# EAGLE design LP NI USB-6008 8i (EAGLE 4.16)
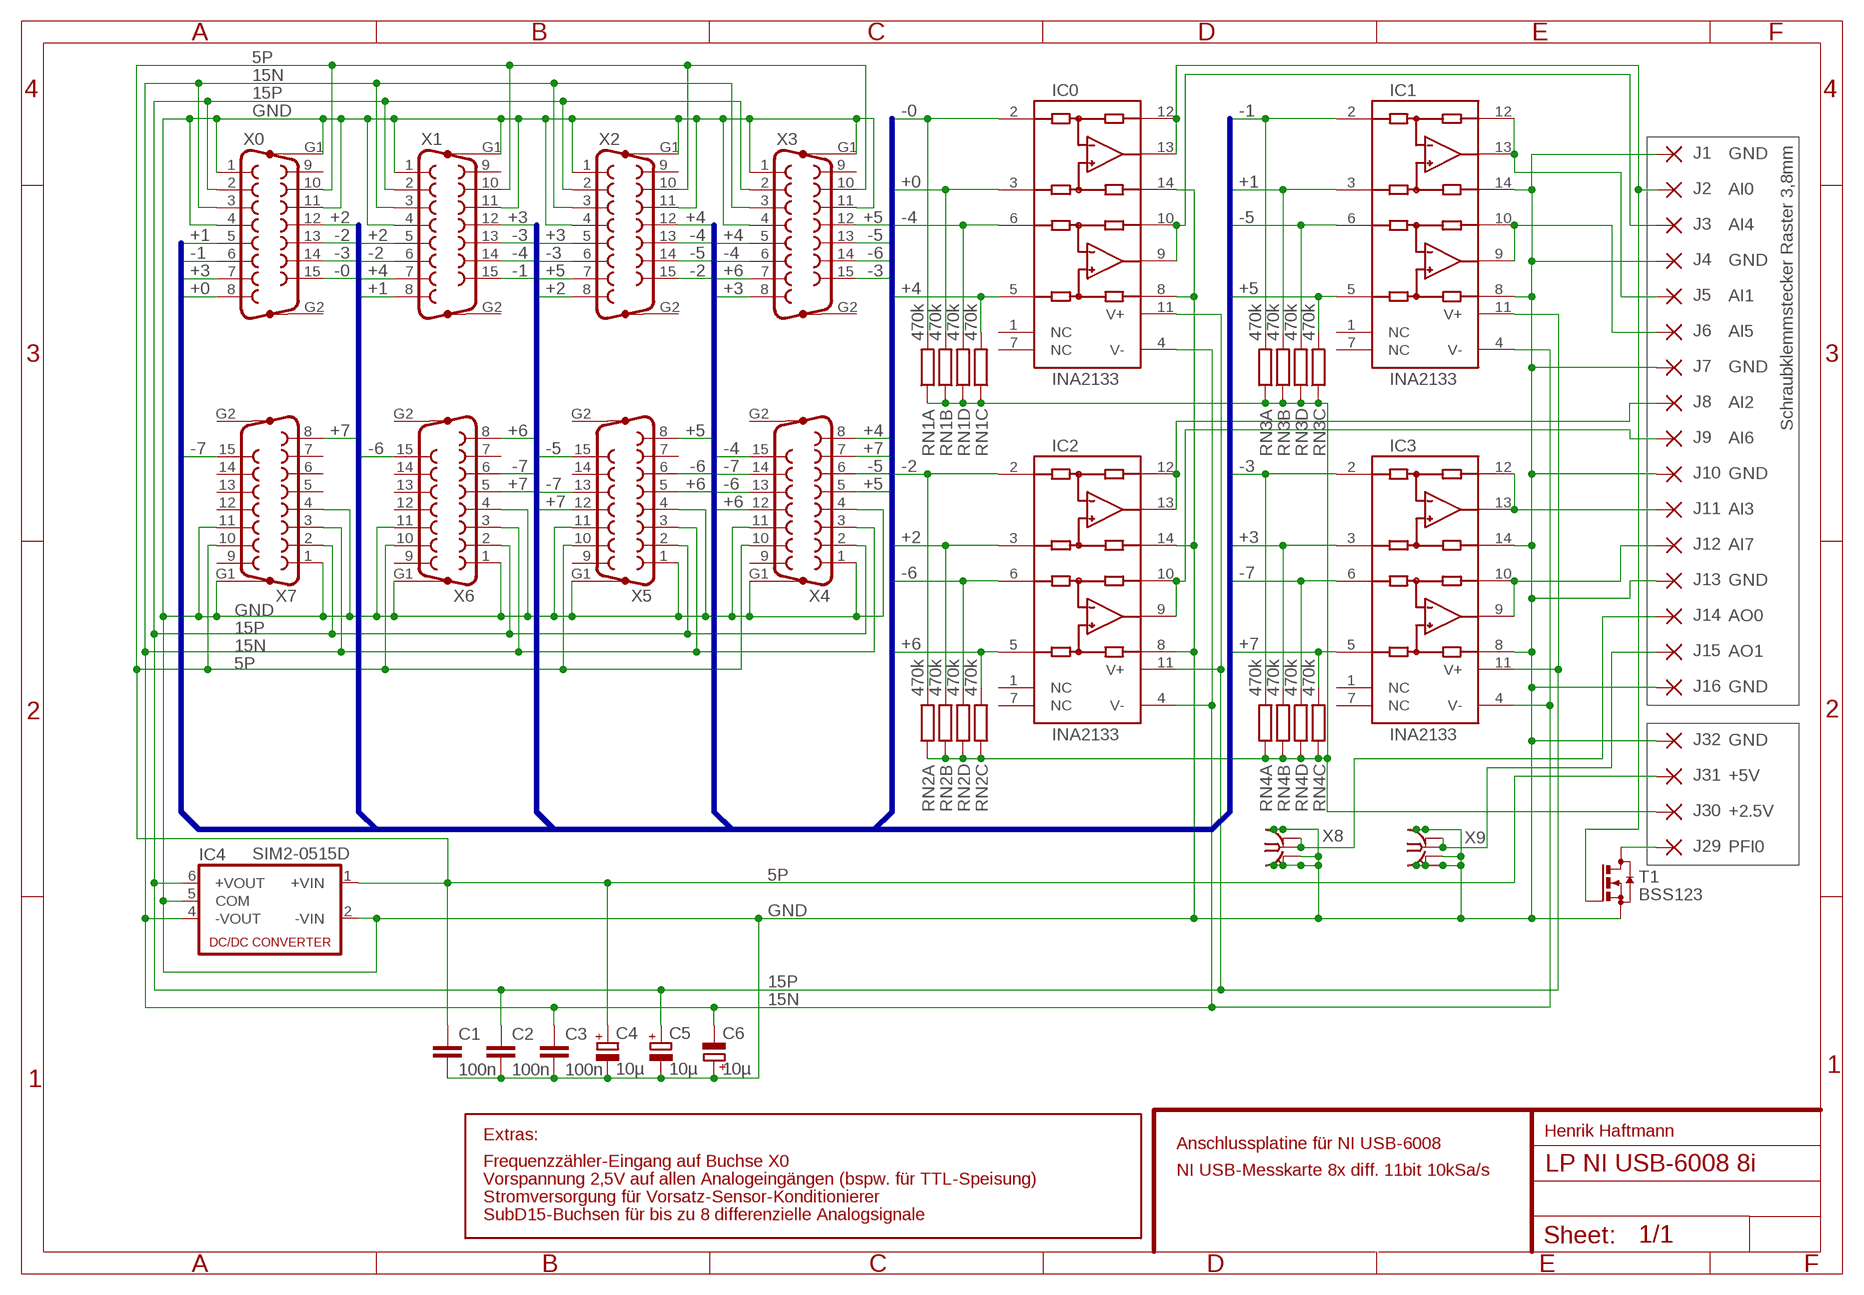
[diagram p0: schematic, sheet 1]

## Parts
C1  100n  C-EUC0603K  [C0603K]
C2  100n  C-EUC0603K  [C0603K]
C3  100n  C-EUC0603K  [C0603K]
C4  10µ  CPOL-EUE2.5-6  [E2,5-6]
C5  10µ  CPOL-EUE2.5-6  [E2,5-6]
C6  10µ  CPOL-EUE2.5-6  [E2,5-6]
IC0  INA2133  INA2134U  [SO14]
IC1  INA2133  INA2134U  [SO14]
IC2  INA2133  INA2134U  [SO14]
IC3  INA2133  INA2134U  [SO14]
IC4  SIM2-0515D  NMA  [NMA]
J1  GND  WIREPAD2,54/1,0  [2,54/1,0]
J2  AI0  WIREPAD2,54/1,0  [2,54/1,0]
J3  AI4  WIREPAD2,54/1,0  [2,54/1,0]
J4  GND  WIREPAD2,54/1,0  [2,54/1,0]
J5  AI1  WIREPAD2,54/1,0  [2,54/1,0]
J6  AI5  WIREPAD2,54/1,0  [2,54/1,0]
J7  GND  WIREPAD2,54/1,0  [2,54/1,0]
J8  AI2  WIREPAD2,54/1,0  [2,54/1,0]
J9  AI6  WIREPAD2,54/1,0  [2,54/1,0]
J10  GND  WIREPAD2,54/1,0  [2,54/1,0]
J11  AI3  WIREPAD2,54/1,0  [2,54/1,0]
J12  AI7  WIREPAD2,54/1,0  [2,54/1,0]
J13  GND  WIREPAD2,54/1,0  [2,54/1,0]
J14  AO0  WIREPAD2,54/1,0  [2,54/1,0]
J15  AO1  WIREPAD2,54/1,0  [2,54/1,0]
J16  GND  WIREPAD2,54/1,0  [2,54/1,0]
J29  PFI0  WIREPAD2,54/1,0  [2,54/1,0]
J30  +2.5V  WIREPAD2,54/1,0  [2,54/1,0]
J31  +5V  WIREPAD2,54/1,0  [2,54/1,0]
J32  GND  WIREPAD2,54/1,0  [2,54/1,0]
RN1  470k  RN-4P1206  [R-4P]
RN2  470k  RN-4P1206  [R-4P]
RN3  470k  RN-4P1206  [R-4P]
RN4  470k  RN-4P1206  [R-4P]
T1  BSS123  [SOT23]
X0  F15VP  [F15VP]
X1  F15VP  [F15VP]
X2  F15VP  [F15VP]
X3  F15VP  [F15VP]
X4  F15VP  [F15VP]
X5  F15VP  [F15VP]
X6  F15VP  [F15VP]
X7  F15VP  [F15VP]
X8  BU-BNC  [BU-BNC]
X9  BU-BNC  [BU-BNC]

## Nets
2P5: J30.1(P) RN1.1 RN1.2 RN1.3 RN1.4 RN2.1 RN2.2 RN2.3 RN2.4 RN3.1 RN3.2 RN3.3 RN3.4 RN4.1 RN4.2 RN4.3 RN4.4
5P: C1.1 C4.+ IC4.1(+VIN) J31.1(P) X0.10 X1.10 X2.10 X3.10 X4.10 X5.10 X6.10 X7.10
15N: C3.1 C6.- IC0.4(V-) IC1.4(V-) IC2.4(V-) IC3.4(V-) IC4.4(-VOUT) X0.3 X1.3 X2.3 X3.3 X4.3 X5.3 X6.3 X7.3
15P: C2.1 C5.+ IC0.11(V+) IC1.11(V+) IC2.11(V+) IC3.11(V+) IC4.6(+VOUT) X0.2 X1.2 X2.2 X3.2 X4.2 X5.2 X6.2 X7.2
+0: IC0.3(+INA) RN1.7 X0.8
+1: IC1.3(+INA) RN3.7 X0.5 X1.8
+2: IC2.3(+INA) RN2.7 X0.12 X1.5 X2.8
+3: IC3.3(+INA) RN4.7 X0.7 X1.12 X2.5 X3.8
+4: IC0.5(+INB) RN1.6 X1.7 X2.12 X3.5 X4.8
+5: IC1.5(+INB) RN3.6 X2.7 X3.12 X4.5 X5.8
+6: IC2.5(+INB) RN2.6 X3.7 X4.12 X5.5 X6.8
+7: IC3.5(+INB) RN4.6 X4.7 X5.12 X6.5 X7.8
-0: IC0.2(-INA) RN1.8 X0.15
-1: IC1.2(-INA) RN3.8 X0.6 X1.15
-2: IC2.2(-INA) RN2.8 X0.13 X1.6 X2.15
-3: IC3.2(-INA) RN4.8 X0.14 X1.13 X2.6 X3.15
-4: IC0.6(-INB) RN1.5 X1.14 X2.13 X3.6 X4.15
-5: IC1.6(-INB) RN3.5 X2.14 X3.13 X4.6 X5.15
-6: IC2.6(-INB) RN2.5 X3.14 X4.13 X5.6 X6.15
-7: IC3.6(-INB) RN4.5 X4.14 X5.13 X6.6 X7.15
AI0: IC0.12(SENSEA) IC0.13(OUTA) J2.1(P) T1.1(G)
AI1: IC1.12(SENSEA) IC1.13(OUTA) J5.1(P)
AI2: IC2.12(SENSEA) IC2.13(OUTA) J8.1(P)
AI3: IC3.12(SENSEA) IC3.13(OUTA) J11.1(P)
AI4: IC0.9(OUTB) IC0.10(SENSEB) J3.1(P)
AI5: IC1.9(OUTB) IC1.10(SENSEB) J6.1(P)
AI6: IC2.9(OUTB) IC2.10(SENSEB) J9.1(P)
AI7: IC3.9(OUTB) IC3.10(SENSEB) J12.1(P)
AO0: J14.1(P) X8.1 X8.1A
AO1: J15.1(P) X9.1 X9.1A
GND: C1.2 C2.2 C3.2 C4.- C5.- C6.+ IC0.8(REFB) IC0.14(REFA) IC1.8(REFB) IC1.14(REFA) IC2.8(REFB) IC2.14(REFA) IC3.8(REFB) IC3.14(REFA) IC4.2(-VIN) IC4.5(COM) J1.1(P) J4.1(P) J7.1(P) J10.1(P) J13.1(P) J16.1(P) J32.1(P) T1.2(S) X0.1 X0.4 X0.11 X0.G1 X1.1 X1.4 X1.11 X1.G1 X2.1 X2.4 X2.11 X2.G1 X3.1 X3.4 X3.11 X3.G1 X4.1 X4.4 X4.11 X4.G1 X5.1 X5.4 X5.11 X5.G1 X6.1 X6.4 X6.11 X6.G1 X7.1 X7.4 X7.11 X7.G1 X8.2 X8.2A X8.3 X8.3A X8.3B X8.4 X8.4A X8.4B X9.2 X9.2A X9.3 X9.3A X9.3B X9.4 X9.4A X9.4B
N$1: J29.1(P) T1.3(D)
Unconnected: IC0.1(NC) IC0.7(NC) IC1.1(NC) IC1.7(NC) IC2.1(NC) IC2.7(NC) IC3.1(NC) IC3.7(NC) X0.9 X0.G2 X1.9 X1.G2 X2.9 X2.G2 X3.9 X3.G2 X4.9 X4.G2 X5.7 X5.9 X5.14 X5.G2 X6.7 X6.9 X6.12 X6.13 X6.14 X6.G2 X7.5 X7.6 X7.7 X7.9 X7.12 X7.13 X7.14 X7.G2

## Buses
+[0..7],-[0..7]

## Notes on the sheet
- Schraubklemmstecker Raster 3,8mm
- Extras: | Henrik Haftmann
- Anschlussplatine für NI USB-6008
- Frequenzzähler-Eingang auf Buchse X0
- NI USB-Messkarte 8x diff. 11bit 10kSa/s
- Vorspannung 2,5V auf allen Analogeingängen (bspw. für TTL-Speisung)
- Stromversorgung für Vorsatz-Sensor-Konditionierer
- SubD15-Buchsen für bis zu 8 differenzielle Analogsignale

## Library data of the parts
C1-C3 = rcl:C-EU: CAPACITOR, European symbol
C4-C6 = rcl:CPOL-EU: POLARIZED CAPACITOR, European symbol
IC0 IC1-IC3 = burr-brown:INA2134: Audio Differential Line Receivers 0dB, G=1
IC4 = dc-dc-converter:NMA: DC-DC CONVERTER
J1-J16 J29-J32 = wirepad:WIREPAD: Wire PAD connect wire on PCB
RN1-RN4 = DiffV:RN-4P: Widerstandsnetzwerk 4 Parallel
T1 = transistor-small-signal:BSS123: N-CHANNEL MOS FET
X0 X1-X7 = con-subd:F15VP: SUB-D
X8 X9 = Trigger-EA:BU-BNC: BNC-Buchse von Schneider

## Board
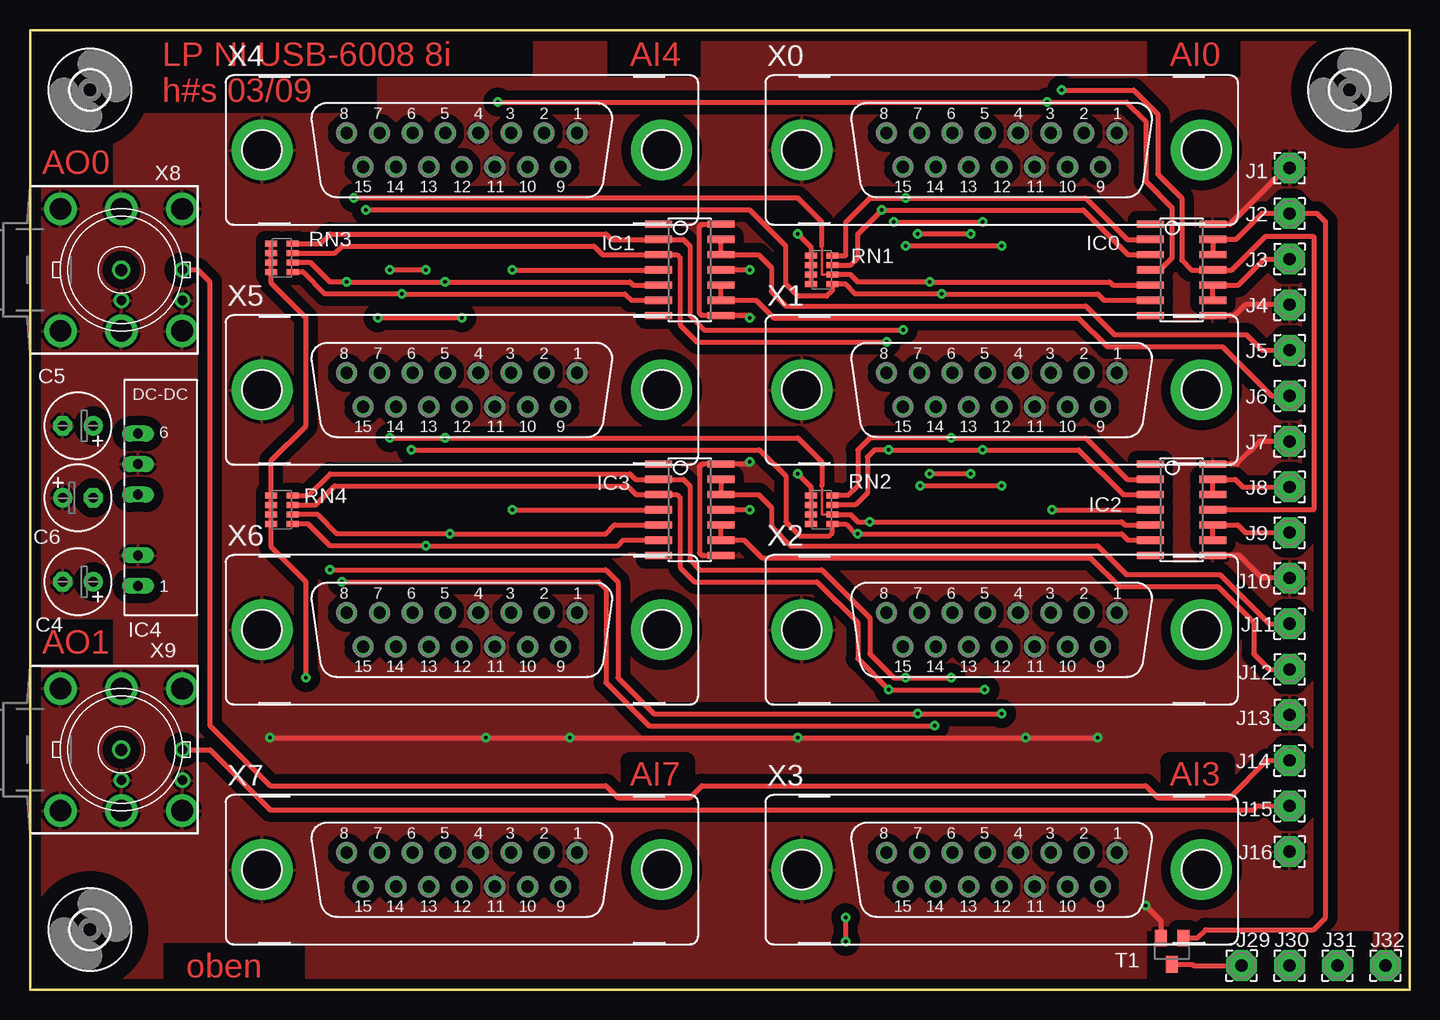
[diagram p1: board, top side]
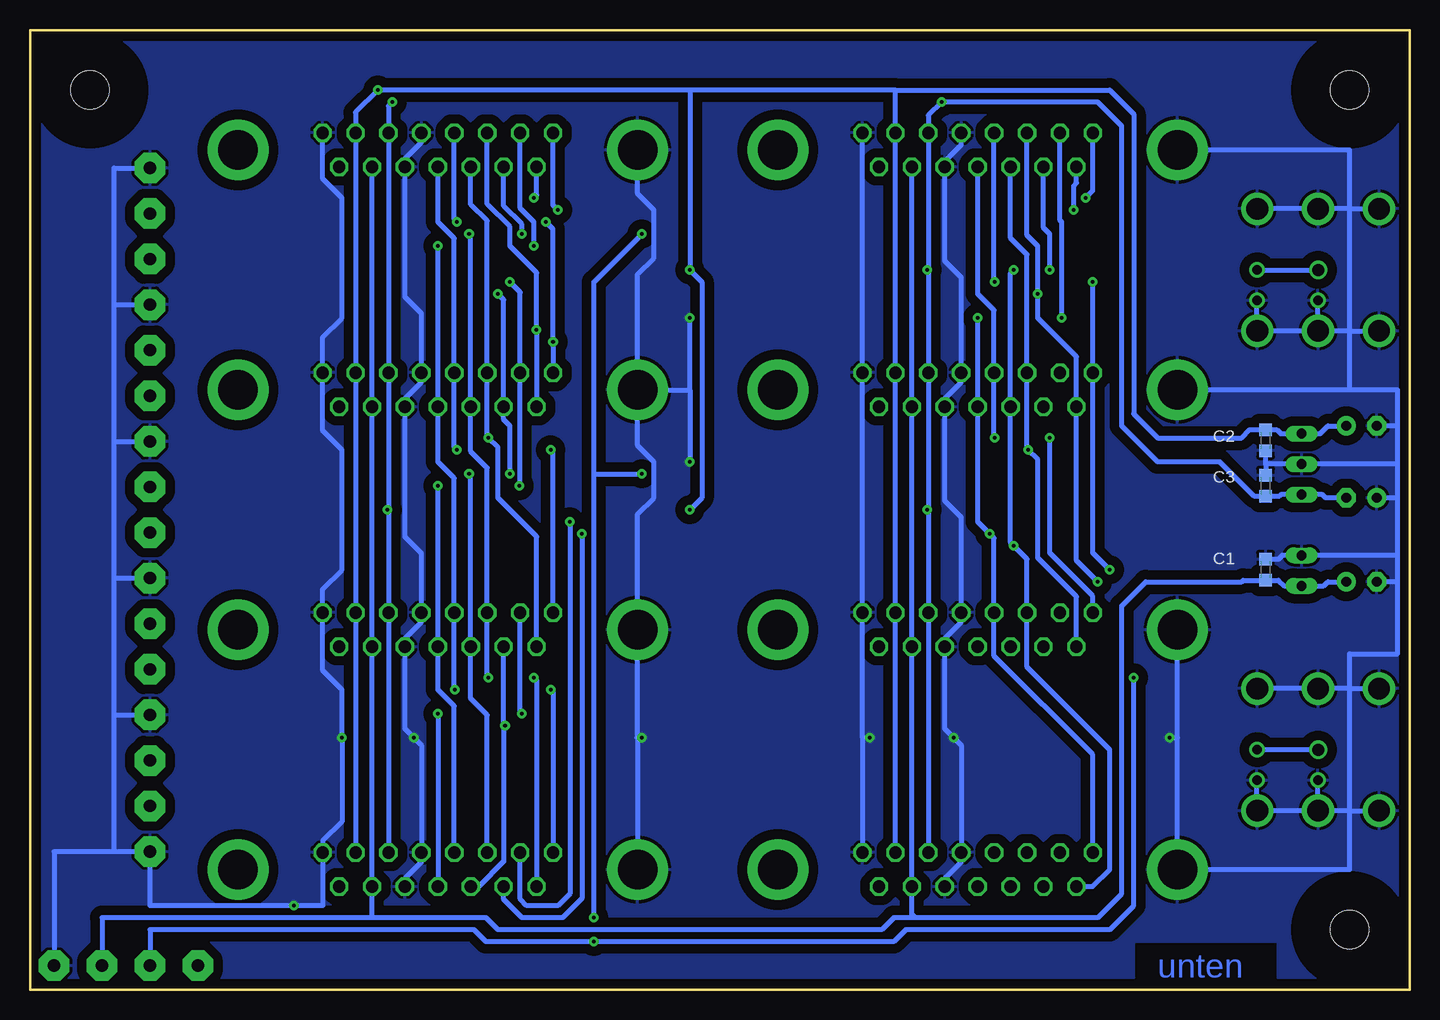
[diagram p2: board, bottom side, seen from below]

Size 115 x 80 mm. Coordinates in mm from the lower left corner, seen from the top.
Outline: 0,0 115,0 115,80 0,80 0,0
Copper layers (1*16): Top 0.035mm / dielectric 1.5mm / Bottom 0.035mm
Design rules "Felber": minimum track width 0.15mm, minimum drill 0.3mm, track to track 0.15mm, track to pad 0.15mm, pad to pad 0.15mm, via to via 0.15mm, smd to smd 0mil, copper to edge 0.3mm, drill to drill 0.3mm, minimum pad ring 10mil, minimum via ring 8mil, stop-mask expansion 4mil, vias tented up to drill 0mil, thermal gap 10mil

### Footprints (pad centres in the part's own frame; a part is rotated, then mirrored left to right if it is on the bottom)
C0603K = smd 1.05 x 1.08: 1 -0.875,0; 2 0.875,0
E2,5-6 = drill 0.813 pad 1.6 round: + -1.27,0 | drill 0.813 pad 1.6 octagon: - 1.27,0
SO14 = smd 0.61 x 2.21: 1 -3.81,-2.603; 2 -2.54,-2.603; 3 -1.27,-2.603; 4 0,-2.603; 5 1.27,-2.603; 6 2.54,-2.603; 7 3.81,-2.603; 8 3.81,2.603; 9 2.54,2.603; 10 1.27,2.603; 11 0,2.603; 12 -1.27,2.603; 13 -2.54,2.603; 14 -3.81,2.603
NMA = drill 0.813 long: 1 0,6.35; 2 0,3.81; 4 0,-1.27; 5 0,-3.81; 6 0,-6.35
2,54/1,0 = drill 1.016 pad 2.54 octagon: 1 0,0
R-4P = smd 0.5 x 1: 1 -1.2,-0.88; 2 -0.4,-0.88; 3 0.4,-0.88; 4 1.2,-0.88; 5 1.2,0.88; 6 0.4,0.88; 7 -0.4,0.88; 8 -1.2,0.88
SOT23 = smd 1 x 1.4: 1 -0.95,-1.1; 2 0.95,-1.1; 3 0,1.1
3,2 = hole 3.2: 0,0
F15VP = drill 1.016 octagon: 1 9.601,1.422; 2 6.858,1.422; 3 4.115,1.422; 4 1.372,1.422; 5 -1.372,1.422; 6 -4.115,1.422; 7 -6.858,1.422; 8 -9.601,1.422; 9 8.23,-1.422; 10 5.486,-1.422; 11 2.743,-1.422; 12 0,-1.422; 13 -2.743,-1.422; 14 -5.486,-1.422; 15 -8.23,-1.422 | drill 3.302 pad 5.08 round: G1 -16.662,0; G2 16.662,0
BU-BNC = drill 0.8 round: 1 -12.7,0; 2 -12.71,2.55; 2A -7.63,2.55 | drill 1 round: 1A -7.62,0 | drill 1.8 round: 3 -7.61,5.09; 3A -12.69,5.09; 3B -2.53,5.09; 4 -7.61,-5.09; 4A -2.53,-5.09; 4B -12.69,-5.09

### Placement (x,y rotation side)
C1  12,35 90 bottom
C2  12,45.8 270 bottom
C3  12,42 90 bottom
C4  4,34 180 top
C5  4,47 180 top
C6  4,41 0 top
IC0  96,60 270 top
IC1  55,60 270 top
IC2  96,40 270 top
IC3  55,40 270 top
IC4  9,40 180 top
J1  105,68.5 0 top
J2  105,64.7 0 top
J3  105,60.9 0 top
J4  105,57.1 0 top
J5  105,53.3 0 top
J6  105,49.5 0 top
J7  105,45.7 0 top
J8  105,41.9 0 top
J9  105,38.1 0 top
J10  105,34.3 0 top
J11  105,30.5 0 top
J12  105,26.7 0 top
J13  105,22.9 0 top
J14  105,19.1 0 top
J15  105,15.3 0 top
J16  105,11.5 0 top
J29  101,2 0 top
J30  105,2 0 top
J31  109,2 0 top
J32  113,2 0 top
RN1  66,60 270 top
RN2  66,40 270 top
RN3  21,61 270 top
RN4  21,40 270 top
T1  95.2,3.2 180 top
U$1  [3,2]  5,75 0 top
U$2  [3,2]  5,5 0 top
U$3  [3,2]  110,75 0 top
X0  81,70 0 top
X1  81,50 0 top
X2  81,30 0 top
X3  81,10 0 top
X4  36,70 0 top
X5  36,50 0 top
X6  36,30 0 top
X7  36,10 0 top
X8  0,60 180 top
X9  0,20 180 top

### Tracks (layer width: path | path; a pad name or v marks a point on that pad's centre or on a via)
2P5  (via drill 0.3 pad 0.8)
  Top 0.4: RN2.4 RN2.3 RN2.2 RN2.1 65.12,41.88 v64,43 | RN1.4 RN1.3 RN1.2 RN1.1 65.12,61.88 v64,63 | v23,26 23,34 20.12,36.88 RN4.4 RN4.3 RN4.2 RN4.1 20.12,44.12 23,47 23,56 20.12,58.88 RN3.4 RN3.3 RN3.2 RN3.1 | v68,4 v68,6
  Bottom 0.4: J30.1 105,5 78,5 77,4 v68,4 43,4 42,5 25,5 23,7 v23,26 | v64,63 68,59 68,43 | 68,43 v64,43 | v68,6 68,43
5P
  Bottom 0.4: X0.10 X1.10 X2.10 X3.10 86.49,6 | J31.1 109,6 86.49,6 | X4.10 X5.10 X6.10 X7.10 41.49,6.29 41.2,6 | 41.2,6 26,6 24,8 24,32 22,34 14,34 13.88,34.12 C1.1 10.93,34.12 10.45,33.65 IC4.1 7.15,33.65 6.8,34 C4.+ | 86.49,6 77,6 76,5 44,5 43,6 41.2,6
15N  (via drill 0.3 pad 0.8)
  Top 0.4: v85.2,40 IC2.4 | v40.2,40 IC3.4 | v40.2,60 IC1.4 | v39,74 v84.8,74 91.4,74 93,72.4 93,67.4 95.2,65.2 95.2,61 94.2,60 IC0.4
  Bottom 0.4: 85.11,40 X2.3 X3.3 | 85.11,40 X1.3 X0.3 85.11,73.69 v84.8,74 | 85.11,40 v85.2,40 | 40.11,60 X5.3 40.11,40 | 40.11,60 X4.3 40.11,72.89 v39,74 26,74 24,72 24,47 21,44 15.8,44 12.93,41.12 C3.1 10.88,41.12 10.73,41.27 IC4.4 7.27,41.27 7,41 C6.- | 40.11,40 X6.3 X7.3 | 40.11,40 v40.2,40 | 40.11,60 v40.2,60
15P  (via drill 0.3 pad 0.8)
  Top 0.4: IC2.11 107,40 107,62.8 103,62.8 100.2,60 IC0.11 96.8,60 96,60.8 96,66 94,68 94,73 92,75 v86,75 | v60,60 IC1.11 | v60,40 IC3.11
  Bottom 0.4: X3.2 X2.2 X1.2 X0.2 87.86,73.14 v86,75 60,75 | X7.2 X6.2 X5.2 X4.2 42.86,75 43,75 | v60,40 59,41 59,59 v60,60 60,75 | 43,75 60,75 | 43,75 25,75 23,73 23,48 21,46 14,46 13.32,46.67 C2.1 11.07,46.67 10.75,46.35 IC4.6 7.45,46.35 6.8,47 C5.+
+0  (via drill 0.3 pad 0.8)
  Top 0.4: IC0.3 91.53,61.27 87.8,65 v71,65 69,63 69,61 68.4,60.4 RN1.7
  Bottom 0.4: X0.8 71.4,65.4 v71,65
+1  (via drill 0.3 pad 0.8)
  Top 0.4: v72,64 v79.4,64 | v71.4,54 55.6,54 54.2,55.4 54.2,61 53.93,61.27 IC1.3 47.73,61.27 47,62 26,62 25.4,61.4 RN3.7
  Bottom 0.4: X0.5 79.63,64.23 v79.4,64 | v71.4,54 X1.8 | v71.4,54 | v71.4,54 71.4,63.4 v72,64
+2  (via drill 0.3 pad 0.8)
  Top 0.4: RN2.7 68.8,40.4 69.8,41.4 69.8,44.4 70.4,45 v71.6,45 v79.4,45 87.4,45 91.13,41.27 IC2.3
  Bottom 0.4: X0.12 81,64 79.63,62.63 X1.5 79.63,45.23 v79.4,45 | X2.8 71.4,44.8 v71.6,45
+3  (via drill 0.3 pad 0.8)
  Top 0.4: v81,62 v73,62 | v79.6,25 v71.6,25 69,27.6 69,30.6 65.6,34 55.4,34 54.2,35.2 54.2,41 53.93,41.27 IC3.3 50.53,41.27 49.8,42 25.4,42 23.8,40.4 RN4.7
  Bottom 0.4: v81,62 X1.12 81,44 79.63,42.63 X2.5 79.63,25.03 v79.6,25 | X0.7 74.14,65.14 73,64 v73,62 | X3.8 71.4,24.8 v71.6,25
+4  (via drill 0.3 pad 0.8)
  Top 0.2: RN1.6 66,59.6 66,62
  Top 0.4: RN1.6 68.4,59.6 69,59 v75,59 90,59 90.27,58.73 IC0.5 | v81,42 v74.2,42 | 66,62 66,64 64,66 v27,66
  Bottom 0.4: v75,59 74.14,58.14 X1.7 74.14,42.06 v74.2,42 | v81,42 X2.12 81,25 79.63,23.63 X3.5 | X4.8 26.4,66.6 v27,66
+5  (via drill 0.3 pad 0.8)
  Top 0.4: v81,23 v74,23 52,23 49,26 49,34 48,35 v25,35 | IC1.5 50.27,58.73 50,59 v34.6,59 v26.4,59 25,59 23.4,60.6 RN3.6
  Bottom 0.4: X2.7 74.14,23.14 v74,23 | v81,23 X3.12 | v25,35 26.4,36.4 X5.8 v26.4,59 | X4.5 34.63,59.03 v34.6,59
+6  (via drill 0.3 pad 0.8)
  Top 0.2: RN2.6 66,39.6 66,42
  Top 0.4: IC2.5 91.27,38.73 91,39 69,39 | RN2.6 68.4,39.6 69,39 | 69,39 v70,39 | 66,42 66,44 64,46 v34.6,46 v30,46
  Bottom 0.4: X3.7 74.14,7.54 73.6,7 71,7 70,8 v70,39 | X6.8 26.4,32.8 30,36.4 v30,46 | v34.6,46 34.63,46.03 X5.5 34.63,56.63 36,58 X4.12
+7  (via drill 0.3 pad 0.8)
  Top 0.4: IC3.5 48.73,38.73 48,38 v35,38 25.6,38 24,39.6 RN4.6 | v36,56 v29,56
  Bottom 0.4: X7.8 26.4,19.6 34.63,27.83 X6.5 34.63,37.63 v35,38 36,39 X5.12 v36,56 | X4.7 29.14,64.14 29,64 v29,56
-0  (via drill 0.3 pad 0.8)
  Top 0.4: IC0.2 91.46,62.54 88,66 v73,66 70,66 68,64 68,61.2 RN1.8
  Bottom 0.4: X0.15 72.77,66.23 v73,66
-1  (via drill 0.3 pad 0.8)
  Top 0.4: RN3.8 24.2,62.2 25,63 48,63 48.46,62.54 IC1.2 54.46,62.54 55,62 55,56.2 56.2,55 v72.8,55
  Bottom 0.4: X0.6 76.88,65.48 75,63.6 75,62 72.77,59.77 72.77,55 | 72.77,55 X1.15 | v72.8,55 72.77,55
-2  (via drill 0.3 pad 0.8)
  Top 0.4: RN2.8 68.2,41.2 69,42 69,45 70,46 v76.8,46 88,46 91.46,42.54 IC2.2
  Bottom 0.4: X0.13 78.26,65.46 76.88,64.08 X1.6 76.88,46.09 v76.8,46 76,45.2 76,41 72.77,37.77 X2.15
-3  (via drill 0.3 pad 0.8)
  Top 0.4: v78.4,63 v74,63 | v76.8,26 v73,26 72,26 70,28 70,31 66,35 55.8,35 55,35.8 55,42 54.46,42.54 IC3.2 50.46,42.54 50,43 25,43 23.2,41.2 RN4.8
  Bottom 0.4: v78.4,63 78.26,62.86 X1.13 78.26,44.86 76.88,43.48 X2.6 76.88,26 v76.8,26 | X0.14 75.51,65.31 74,63.8 v74,63 | X3.15 72.77,25.77 v73,26
-4  (via drill 0.3 pad 0.8)
  Top 0.4: IC0.6 89.54,57.46 89,58 v76,58 68.8,58 68,58.8 RN1.5 66.88,58.28 66.4,57.8 64,57.8 63,58.8 63,62 60,65 v28,65 | v78.4,43 v75,43
  Bottom 0.4: v76,58 75.51,57.51 X1.14 75.51,47.51 75,47 v75,43 | v78.4,43 78.26,42.86 X2.13 78.26,24.26 76.88,22.89 X3.6 | X4.15 27.77,67.23 28,67 v28,65
-5  (via drill 0.3 pad 0.8)
  Top 0.4: v26,34 47.4,34 48,33.4 48,25.6 51.6,22 v75.4,22 | IC1.6 50.14,57.46 49.6,58 v31,58 24.6,58 22.8,59.8 RN3.5
  Bottom 0.4: 75.51,22 75.51,10.69 77.62,8.58 X3.13 | 75.51,22 X2.14 | v26,34 27.77,35.77 X5.15 27.77,52.77 31,56 v31,58 31,62 31.89,62.88 X4.6 | v75.4,22 75.51,22
-6  (via drill 0.3 pad 0.8)
  Top 0.4: IC2.6 91.54,37.46 91,38 v69,38 68.8,38 68,38.8 RN2.5 66.88,38.08 66.6,37.8 64.2,37.8 63,39 63,42.8 60.8,45 v31.8,45
  Bottom 0.4: X3.14 75.51,7.51 74,6 70.6,6 69,7.6 v69,38 | X6.15 27.77,32.77 31,36 31,44.2 v31.8,45 31.89,45.09 X5.6 31.89,61.28 33.26,62.66 X4.13
-7  (via drill 0.3 pad 0.8)
  Top 0.4: IC3.6 49.46,37.46 49,37 v33,37 25,37 23.2,38.8 RN4.5 | v33,60 v30,60
  Bottom 0.4: X7.15 26.42,8.58 25,10 25,20 31.89,26.89 X6.6 31.89,35.88 v33,37 33.26,37.26 X5.13 33.26,59.74 v33,60 | X4.14 30.51,63.51 30,63 v30,60
AI0
  Top 0.4: IC0.12 IC0.13 100.54,62.54 102.7,64.7 J2.1 107.3,64.7 108,64 108,6 107,5 98,5 97.3,4.3 T1.1
AI1
  Top 0.4: J5.1 102.7,53.3 101.4,54.6 90.4,54.6 88,57 63,57 61.8,58.2 61.8,60.2 60.73,61.27 IC1.12 IC1.13
AI2
  Top 0.4: IC2.12 98.6,41.8 IC2.13 100.46,42.54 101.1,41.9 J8.1
AI3
  Top 0.4: IC3.13 IC3.12 60.73,41.27 61.8,40.2 61.8,38.6 63.4,37 89,37 91.4,34.6 99.2,34.6 103.3,30.5 J11.1
AI4
  Top 0.4: J3.1 102.9,60.9 100.73,58.73 IC0.10 98.6,58 IC0.9
AI5
  Top 0.4: J6.1 103.5,49.5 99.4,53.6 89.8,53.6 87.4,56 62,56 60.54,57.46 IC1.9 IC1.10
AI6
  Top 0.4: IC2.9 98.6,38 IC2.10 100.67,38.73 101.3,38.1 J9.1
AI7
  Top 0.4: IC3.10 IC3.9 59.54,37.46 61,36 88.4,36 90.8,33.6 99,33.6 102,30.6 102,28 103.3,26.7 J12.1
AO0
  Top 0.4: X8.1 14,60 15,59 15,22 20,17 48,17 49,16 55,16 56,17 93,17 94,16 100,16 103.1,19.1 J14.1
  Bottom 0.4: 12.8,60 X8.1 X8.1A
AO1
  Top 0.4: X9.1 15,20 20,15 102,15 102.3,15.3 J15.1
  Bottom 0.4: X9.1A X9.1
GND  (via drill 0.3 pad 0.8)
  Top 0.4: IC2.14 100.61,43.81 102.5,45.7 J7.1 | IC2.8 100.81,36.19 102.7,34.3 J10.1 | IC0.14 100.01,63.81 104.7,68.5 J1.1 | IC0.8 100.39,56.19 101.3,57.1 J4.1 | T1.2 94.25,5.75 v93,7 | IC3.8 56.01,36.19 55.8,36.4 55.8,43.6 56.01,43.81 IC3.14 59.81,43.81 v60,44 | IC1.14 56.01,63.81 55.8,63.6 55.8,56.4 56.01,56.19 IC1.8 59.81,56.19 v60,56 | v20,21 v38,21 v45,21 v64,21 v83,21 v89,21
  Bottom 0.4: X0.4 82.37,70.63 83.74,69.26 X0.11 83.74,57.74 82.37,56.37 X1.4 82.37,50.63 83.74,49.26 X1.11 83.74,37.74 82.37,36.37 X2.4 82.37,30.63 83.74,29.26 X2.11 83.74,21.74 v83,21 82.37,20.37 X3.4 82.37,10.63 83.74,9.26 X3.11 | X0.1 90.6,67.6 89,66 89,56 90.6,54.4 X1.1 90.6,46.6 89,45 89,35 90.6,33.4 X2.1 90.6,26.6 89,25 v89,21 89,14 90.6,12.4 X3.1 90.6,7 92.8,7 | 108,45.7 J7.1 | J10.1 108,34.3 108,34.4 | 108,34.4 108,45.7 | J4.1 108,57.1 108,57 | 108,45.7 108,57 | J1.1 108,68.5 108,57 | 108,22.9 J13.1 | 108,22.9 108,34.4 | 108,11.5 J16.1 105,7 92.8,7 | 108,11.5 108,22.9 | 108,11.5 113,11.5 J32.1 | 92.8,7 v93,7 | X4.1 X5.1 X6.1 45.6,21 | X4.4 37.37,70.43 38.74,69.06 X4.11 38.74,60.74 37.37,59.37 X5.4 37.37,50.63 38.74,49.26 X5.11 38.74,40.74 37.37,39.37 X6.4 37.37,30.63 38.74,29.26 X6.11 38.74,21.74 v38,21 37.37,20.37 X7.4 37.37,10.63 38.74,9.26 X7.11 | 60,50 v60,44 | 60,50 v60,56 | 60,50 X1.G1 64.4,50 | X0.G1 64.34,66.34 63,65 63,61 64.34,59.66 64.34,50.06 64.4,50 | 64.4,50 64.34,49.94 64.34,45.34 63,44 63,41 64.34,39.66 X2.G1 64.4,30 64.34,29.94 64.34,21 | 64.34,21 X3.G1 | 19.34,21 X7.G1 5,10 5,15 | 19.34,21 19.34,29.94 19.4,30 | 19.4,30 X6.G1 | 19.4,30 19.34,30.06 | X4.G1 5,70 5,65 | 5,15 5,25 | 5,25 5,25.2 | 5,25.2 5,28 1,28 1,34 | 1,34 1,36.2 | 1,36.2 1,41 | 1,41 1,43.8 | 1,43.8 1,47 | 1,47 1,50 5,50 | 5,50 5,55 | 5,55 5,65 | 5,14.91 X9.3B | 5,14.91 X9.3 | 5,15 5,14.91 | X9.3 | X9.3 X9.3A 12.69,16 12.71,16 X9.2 | 7.61,15 7.6,15 | X9.3 7.61,15 | X9.2A 7.63,15 7.61,15 | 5,25.09 X9.4A | 5,25.2 5,25.09 | 5,25.09 X9.4 | 5,25 5,25.09 | X9.4 | X9.4 X9.4B | 8,36.19 IC4.2 10.61,36.19 10.93,35.88 C1.2 | 5,54.91 X8.3B | 5,54.91 X8.3 | 5,55 5,54.91 | X8.3 7.6,55
  Bottom 0.4: X8.3 X8.3A 12.69,55 12.71,55 | 7.6,55 7.61,55 X8.3 | X8.2A 7.63,55 7.6,55 | 12.71,55 X8.2 | 12.71,55 12.8,55 | 5,65.09 X8.4A | 5,65.09 X8.4 | 5,65 5,65.09 | X8.4 | X8.4 X8.4B | 5,50 X5.G1 | 19.34,21 v20,21 | 64.34,21 64.4,21 | v64,21 64.34,21 | 45.6,21 X7.1 | 8,36.19 8,36.2 | 1,47 C5.- | 1,41 C6.+ | 1,34 C4.- | v45,21 45.6,21 | 1,43.8 1,43.81 IC4.5 12,43.81 12,44 | 8,36.19 1,36.19 1,36.2 | 12,44 C3.2 | 12,44 C2.2
  pour Bottom (isolate 0.8): 114,79 114,1 112,1 99,1 23,1 23,4 11,4 11,1 1,1 1,79
  pour Top (isolate 0.8): 42,79 48,79 48,76 56,76 56,79 93,79 93,76 101,76 101,79 114,79 114,1 112,1 112,5 93,5 93,1 23,1 23,4 11,4 11,1 1,1 1,27 7,27 7,31 1,31 1,67 7,67 7,73 29,73 29,76 42,76
N$1
  Top 0.4: T1.3 96.9,2.1 97,2 J29.1

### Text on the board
Top: LP NI USB-6008 8i | AI4 | AI0 | h#s 03/09 | AO0 | AO1 | AI7 | AI3 | oben
Bottom: unten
